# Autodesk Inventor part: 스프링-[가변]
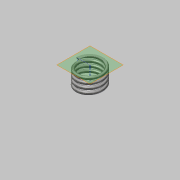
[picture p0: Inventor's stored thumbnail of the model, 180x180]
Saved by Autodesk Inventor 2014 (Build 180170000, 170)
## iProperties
Created: 2015-05
Part Number: 스프링-[가변]
Material: 강철, 탄소
Document SubType Name: Modeling
Designer: Administrator
Density: 7.87 g/cm^3
Appearance: 반연마
Mass: 4.7875 g
Surface Area: 12.5242 cm^2
Volume: 0.608323 cm^3
Author: Administrator
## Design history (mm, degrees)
sketch "스케치1"
  geometry: L1 (0, 0)-(-8, 0); L2 (-8, 0)-(-8, 11.5); L3 (-8, 11.5)-(0, 11.5); L4 (0, 11.5)-(0, 0); C1 r 1 at (-8, 0)
  constraints: 8 end point, 2 parallel, 1 centre point, 1 coincident, 1 horizontal, 1 perpendicular
  dimensions: "d0" = 16 diameter of L2 L4; "d1" = 11.50049 distance between parallel lines of L3 L1 (derived); "d2" = 2 diameter of C1
feature "코일1" pitch "d3" = 10; turns "d5" = 4; dims "d4" = 11.50049 (= d1), "d6" = 0, angle "d7" = 90 deg, angle "d8" = 90 deg, "d9" = 0, "d10" = 0
sketch "스케치2"
  geometry: L1 (9, 0)-(7, 0) reference; 1 further point
  constraints: 1 horizontal alignment
extrude "돌출1" cut sketch "스케치2" stored distance "d11" = 10; taper "d12" = 0 deg
node "작업 평면1"
sketch "스케치3"
  geometry: L1 (-9, 0)-(-7, 0) reference; 1 further point
  constraints: 1 horizontal alignment
extrude "돌출2" cut sketch "스케치3" stored distance "d13" = 10; taper "d14" = 0 deg
node "솔리드1"
node "절단 모서리 투영1"
node "절단 모서리 투영2"
